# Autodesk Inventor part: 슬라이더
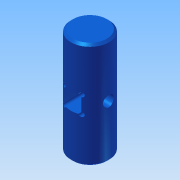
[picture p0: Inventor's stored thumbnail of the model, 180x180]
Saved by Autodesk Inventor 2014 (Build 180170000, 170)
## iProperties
Company: 한국ATC센터
Created: 2015-04
Part Number: 슬라이더
Document SubType Name: Modeling
Designer: KYOUNG IL JANG
Density: 7.85 g/cm^3
Material: 강
Mass: 88.0136 g
Surface Area: 38.9014 cm^2
Volume: 11.2119 cm^3
Appearance: 청록색
Author: KYOUNG IL JANG
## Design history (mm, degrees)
sketch "스케치1"
  geometry: C1 r 9 at (0, 0); 1 further point
  constraints: 1 centre point, 1 coincident
  dimensions: "d0" = 18 diameter of C1
extrude "돌출1" new body sketch "스케치1" stored distance "d1" = 50; taper "d2" = 0 deg
node "작업 평면1"
sketch "스케치3"
  geometry: L1 (4, 25)-(-4, 25); L2 (-4, 25)-(-4, -25); L3 (-4, -25)-(4, -25); L4 (4, -25)-(4, 25); 3 further points
  constraints: 8 end point, 2 midpoint, 2 parallel, 1 horizontal, 1 horizontal alignment, 1 perpendicular, 1 vertical alignment
  dimensions: "d5" = 8 distance of L1.start L1.end; "d6" = 50 distance of L1.end L2.end
extrude "돌출3" cut sketch "스케치3" stored distance "d7" = 8; taper "d8" = 0 deg
sketch "스케치4"
  geometry: 5 further points
hole "구멍1" sketch "스케치4" at (4, 4), (-4, 4), (-4, -4), (4, -4) diameter "d9" = 2; stored, may be unused: countersink angle "d13" = 90 deg, drill point angle "d15" = 118 deg; dims "d10" = 6, "d11" = 4, "d12" = 2, "d14" = 8
node "작업 평면2"
sketch "스케치5"
  geometry: 1 further point
hole "구멍2" sketch "스케치5" at (0, 0) diameter "d16" = 5; stored, may be unused: countersink angle "d20" = 90 deg, drill point angle "d22" = 118 deg; dims "d17" = 6, "d18" = 4, "d19" = 2, "d21" = 8
chamfer "모따기1" distance "d23" = 1; stored, may be unused: second distance "d24" = 2, angle "d25" = 45 deg
node "솔리드1"
mirror "대칭1"
